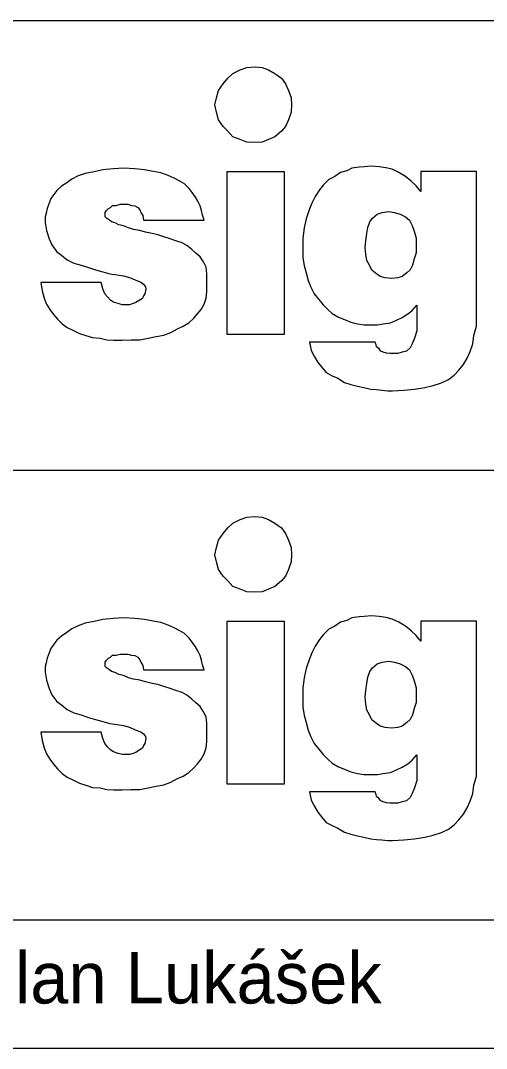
# Model space of a CAD drawing. Extents: x -193 to -151, y 303.3 to 362.7.
# Drawn here: x -158.675 to -156.861, y 343 to 347 of the extents above; entities that cross this region are included whole.
import ezdxf

# ---------------------------------------------------------------- set-up
doc = ezdxf.new("R2010")
doc.units = 0
for name, color, linetype in [('Info o rozpiskách', 7, 'Continuous'), ('popis', 7, 'Continuous'), ('Rozpiska_pole_6', 7, 'Continuous')]:
    doc.layers.add(name, color=color, linetype=linetype)

msp = doc.modelspace()

# ---------------------------------------------------------------- linework, layer by layer
at = {"layer": 'Info o rozpiskách'}
for points in [[(-157.7618, 346.8197), (-157.7338, 346.8178), (-157.7097, 346.8078), (-157.6857, 346.7937), (-157.6597, 346.7757), (-157.6437, 346.7537), (-157.6316, 346.7276), (-157.6216, 346.6996), (-157.6196, 346.6715), (-157.6216, 346.6435), (-157.6316, 346.6134), (-157.6437, 346.5874), (-157.6597, 346.5694), (-157.6857, 346.5473), (-157.7097, 346.5373), (-157.7338, 346.5273), (-157.7618, 346.5253), (-157.7939, 346.5273), (-157.8199, 346.5373), (-157.848, 346.5473), (-157.868, 346.5694), (-157.886, 346.5874), (-157.9041, 346.6134), (-157.9121, 346.6435), (-157.9181, 346.6715), (-157.9121, 346.6996), (-157.9041, 346.7276), (-157.886, 346.7537), (-157.868, 346.7757), (-157.848, 346.7937), (-157.8199, 346.8078), (-157.7939, 346.8178), (-157.7618, 346.8197)], [(-157.7618, 345.0697), (-157.7338, 345.0678), (-157.7097, 345.0578), (-157.6857, 345.0437), (-157.6597, 345.0257), (-157.6437, 345.0037), (-157.6316, 344.9776), (-157.6216, 344.9496), (-157.6196, 344.9215), (-157.6216, 344.8935), (-157.6316, 344.8634), (-157.6437, 344.8374), (-157.6597, 344.8194), (-157.6857, 344.7973), (-157.7097, 344.7873), (-157.7338, 344.7773), (-157.7618, 344.7753), (-157.7939, 344.7773), (-157.8199, 344.7873), (-157.848, 344.7973), (-157.868, 344.8194), (-157.886, 344.8374), (-157.9041, 344.8634), (-157.9121, 344.8935), (-157.9181, 344.9215), (-157.9121, 344.9496), (-157.9041, 344.9776), (-157.886, 345.0037), (-157.868, 345.0257), (-157.848, 345.0437), (-157.8199, 345.0578), (-157.7939, 345.0678), (-157.7618, 345.0697)]]:
    msp.add_lwpolyline(points, dxfattribs=at)
at = {"layer": 'popis'}
for points in [[(-158.1966, 346.2228), (-157.9602, 346.2228), (-157.9662, 346.2428), (-157.9702, 346.2609), (-157.9762, 346.2788), (-157.9842, 346.2969), (-157.9943, 346.3129), (-158.0062, 346.331), (-158.0182, 346.347), (-158.0363, 346.365), (-158.0543, 346.375), (-158.0763, 346.3871), (-158.1004, 346.3971), (-158.1284, 346.4071), (-158.1585, 346.4131), (-158.1925, 346.4191), (-158.2306, 346.4231), (-158.2726, 346.4251), (-158.3147, 346.4231), (-158.3548, 346.4191), (-158.3888, 346.4111), (-158.4229, 346.4051), (-158.451, 346.3951), (-158.475, 346.3831), (-158.495, 346.369), (-158.5151, 346.355), (-158.5331, 346.339), (-158.5451, 346.3229), (-158.5572, 346.3069), (-158.5631, 346.2889), (-158.5712, 346.2688), (-158.5751, 346.2509), (-158.5792, 346.2368), (-158.5792, 346.2147), (-158.5732, 346.1827), (-158.5631, 346.1507), (-158.5531, 346.1266), (-158.5331, 346.1006), (-158.5151, 346.0866), (-158.4931, 346.0685), (-158.467, 346.0565), (-158.439, 346.0485), (-158.4109, 346.0385), (-158.3828, 346.0305), (-158.3548, 346.0225), (-158.3268, 346.0144), (-158.2987, 346.0105), (-158.2747, 346.0065), (-158.2506, 346.0004), (-158.2286, 345.9904), (-158.2066, 345.9824), (-158.1966, 345.9744), (-158.1885, 345.9644), (-158.1865, 345.9544), (-158.1906, 345.9363), (-158.1966, 345.9283), (-158.2006, 345.9183), (-158.2126, 345.9103), (-158.2266, 345.9022), (-158.2366, 345.8983), (-158.2506, 345.8943), (-158.2647, 345.8943), (-158.2787, 345.8943), (-158.2947, 345.8983), (-158.3128, 345.9043), (-158.3228, 345.9103), (-158.3368, 345.9243), (-158.3468, 345.9363), (-158.3548, 345.9563), (-158.3608, 345.9804), (-158.5952, 345.9804), (-158.5912, 345.9484), (-158.5832, 345.9203), (-158.5732, 345.8962), (-158.5612, 345.8762), (-158.5471, 345.8562), (-158.5311, 345.8381), (-158.5131, 345.8202), (-158.4931, 345.8061), (-158.469, 345.7941), (-158.445, 345.7821), (-158.4209, 345.7741), (-158.3949, 345.7661), (-158.3648, 345.764), (-158.3388, 345.758), (-158.3128, 345.756), (-158.2787, 345.756), (-158.2446, 345.758), (-158.2106, 345.758), (-158.1785, 345.764), (-158.1465, 345.77), (-158.1165, 345.7761), (-158.0904, 345.7861), (-158.0643, 345.8001), (-158.0423, 345.8102), (-158.0203, 345.8241), (-158.0002, 345.8422), (-157.9862, 345.8582), (-157.9722, 345.8762), (-157.9602, 345.8962), (-157.9522, 345.9203), (-157.9501, 345.9443), (-157.9501, 345.9684), (-157.9501, 345.9744), (-157.9501, 345.9804), (-157.9501, 345.9864), (-157.9501, 345.9924), (-157.9501, 346.0004), (-157.9501, 346.0065), (-157.9501, 346.0105), (-157.9501, 346.0144), (-157.9522, 346.0405), (-157.9622, 346.0605), (-157.9762, 346.0806), (-157.9922, 346.0946), (-158.0082, 346.1086), (-158.0282, 346.1246), (-158.0463, 346.1347), (-158.0703, 346.1427), (-158.0924, 346.1507), (-158.1165, 346.1587), (-158.1404, 346.1667), (-158.1625, 346.1707), (-158.1885, 346.1767), (-158.2106, 346.1827), (-158.2346, 346.1868), (-158.2547, 346.1928), (-158.2747, 346.2007), (-158.2927, 346.2047), (-158.3067, 346.2128), (-158.3207, 346.2168), (-158.3288, 346.2228), (-158.3407, 346.2308), (-158.3448, 346.2368), (-158.3448, 346.2448), (-158.3448, 346.2528), (-158.3407, 346.2609), (-158.3328, 346.2688), (-158.3247, 346.2729), (-158.3168, 346.2809), (-158.3027, 346.2809), (-158.2867, 346.2849), (-158.2726, 346.2849), (-158.2566, 346.2849), (-158.2426, 346.2809), (-158.2306, 346.2788), (-158.2186, 346.2729), (-158.2106, 346.2628), (-158.2066, 346.2528), (-158.1985, 346.2408), (-158.1966, 346.2228)], [(-157.872, 346.4111), (-157.872, 345.78), (-157.6477, 345.78), (-157.6477, 346.4111), (-157.872, 346.4111)], [(-157.1168, 346.4131), (-157.1168, 346.335), (-157.1349, 346.357), (-157.1549, 346.375), (-157.1769, 346.3931), (-157.203, 346.4091), (-157.229, 346.4211), (-157.253, 346.4271), (-157.2791, 346.4312), (-157.3091, 346.4331), (-157.3372, 346.4312), (-157.3572, 346.4291), (-157.3852, 346.4251), (-157.4053, 346.4151), (-157.4293, 346.4091), (-157.4513, 346.3931), (-157.4754, 346.381), (-157.4954, 346.361), (-157.5115, 346.341), (-157.5275, 346.315), (-157.5415, 346.2889), (-157.5515, 346.2628), (-157.5635, 346.2288), (-157.5715, 346.1928), (-157.5756, 346.1527), (-157.5756, 346.1106), (-157.5756, 346.0765), (-157.5715, 346.0465), (-157.5635, 346.0184), (-157.5555, 345.9884), (-157.5455, 345.9624), (-157.5315, 345.9363), (-157.5134, 345.9143), (-157.4974, 345.8943), (-157.4794, 345.8762), (-157.4613, 345.8602), (-157.4374, 345.8462), (-157.4133, 345.8362), (-157.3893, 345.8262), (-157.3632, 345.8202), (-157.3372, 345.8161), (-157.3091, 345.8161), (-157.285, 345.8161), (-157.263, 345.8202), (-157.235, 345.8241), (-157.2109, 345.8341), (-157.1889, 345.8441), (-157.1669, 345.8582), (-157.1509, 345.8722), (-157.1328, 345.8922), (-157.1328, 345.8341), (-157.1328, 345.7921), (-157.1409, 345.764), (-157.1509, 345.742), (-157.1589, 345.726), (-157.1729, 345.714), (-157.1889, 345.71), (-157.2069, 345.704), (-157.2269, 345.704), (-157.237, 345.704), (-157.251, 345.7059), (-157.263, 345.71), (-157.2731, 345.714), (-157.2791, 345.7219), (-157.2891, 345.73), (-157.2911, 345.738), (-157.2951, 345.748), (-157.5495, 345.748), (-157.5435, 345.7159), (-157.5315, 345.694), (-157.5175, 345.6699), (-157.5034, 345.6519), (-157.4854, 345.6299), (-157.4613, 345.6178), (-157.4393, 345.6078), (-157.4133, 345.5918), (-157.3893, 345.5837), (-157.3632, 345.5778), (-157.3391, 345.5718), (-157.3111, 345.5658), (-157.2891, 345.5637), (-157.269, 345.5617), (-157.245, 345.5597), (-157.2269, 345.5597), (-157.1829, 345.5617), (-157.1409, 345.5658), (-157.1008, 345.5718), (-157.0687, 345.5797), (-157.0367, 345.5897), (-157.0086, 345.6038), (-156.9866, 345.6198), (-156.9686, 345.6399), (-156.9505, 345.6619), (-156.9365, 345.6859), (-156.9245, 345.7119), (-156.9145, 345.742), (-156.9105, 345.7741), (-156.9005, 345.8102), (-156.9005, 345.8482), (-156.9005, 345.8922), (-156.9005, 346.4131), (-157.1168, 346.4131)], [(-157.241, 346.2568), (-157.219, 346.2528), (-157.1969, 346.2468), (-157.1769, 346.2368), (-157.1609, 346.2228), (-157.1509, 346.2028), (-157.1428, 346.1807), (-157.1349, 346.1527), (-157.1349, 346.1226), (-157.1349, 346.0966), (-157.1428, 346.0725), (-157.1488, 346.0485), (-157.1589, 346.0305), (-157.1709, 346.0184), (-157.1889, 346.0044), (-157.2069, 345.9984), (-157.231, 345.9965), (-157.255, 345.9984), (-157.275, 346.0044), (-157.2951, 346.0184), (-157.3071, 346.0285), (-157.3171, 346.0485), (-157.3271, 346.0665), (-157.3312, 346.0906), (-157.3331, 346.1166), (-157.3312, 346.1447), (-157.3271, 346.1707), (-157.3231, 346.1947), (-157.3152, 346.2168), (-157.3051, 346.2308), (-157.2871, 346.2468), (-157.2671, 346.2528), (-157.241, 346.2568)], [(-157.1168, 344.6631), (-157.1168, 344.585), (-157.1349, 344.607), (-157.1549, 344.625), (-157.1769, 344.6431), (-157.203, 344.6591), (-157.229, 344.6711), (-157.253, 344.6771), (-157.2791, 344.6812), (-157.3091, 344.6831), (-157.3372, 344.6812), (-157.3572, 344.6791), (-157.3852, 344.6751), (-157.4053, 344.6651), (-157.4293, 344.6591), (-157.4513, 344.6431), (-157.4754, 344.631), (-157.4954, 344.611), (-157.5115, 344.591), (-157.5275, 344.565), (-157.5415, 344.5389), (-157.5515, 344.5128), (-157.5635, 344.4788), (-157.5715, 344.4428), (-157.5756, 344.4027), (-157.5756, 344.3606), (-157.5756, 344.3265), (-157.5715, 344.2965), (-157.5635, 344.2684), (-157.5555, 344.2384), (-157.5455, 344.2124), (-157.5315, 344.1863), (-157.5134, 344.1643), (-157.4974, 344.1443), (-157.4794, 344.1262), (-157.4613, 344.1102), (-157.4374, 344.0962), (-157.4133, 344.0862), (-157.3893, 344.0762), (-157.3632, 344.0702), (-157.3372, 344.0661), (-157.3091, 344.0661), (-157.285, 344.0661), (-157.263, 344.0702), (-157.235, 344.0741), (-157.2109, 344.0841), (-157.1889, 344.0941), (-157.1669, 344.1082), (-157.1509, 344.1222), (-157.1328, 344.1422), (-157.1328, 344.0841), (-157.1328, 344.0421), (-157.1409, 344.014), (-157.1509, 343.992), (-157.1589, 343.976), (-157.1729, 343.964), (-157.1889, 343.96), (-157.2069, 343.954), (-157.2269, 343.954), (-157.237, 343.954), (-157.251, 343.9559), (-157.263, 343.96), (-157.2731, 343.964), (-157.2791, 343.9719), (-157.2891, 343.98), (-157.2911, 343.988), (-157.2951, 343.998), (-157.5495, 343.998), (-157.5435, 343.9659), (-157.5315, 343.944), (-157.5175, 343.9199), (-157.5034, 343.9019), (-157.4854, 343.8799), (-157.4613, 343.8678), (-157.4393, 343.8578), (-157.4133, 343.8418), (-157.3893, 343.8337), (-157.3632, 343.8278), (-157.3391, 343.8218), (-157.3111, 343.8158), (-157.2891, 343.8137), (-157.269, 343.8117), (-157.245, 343.8097), (-157.2269, 343.8097), (-157.1829, 343.8117), (-157.1409, 343.8158), (-157.1008, 343.8218), (-157.0687, 343.8297), (-157.0367, 343.8397), (-157.0086, 343.8538), (-156.9866, 343.8698), (-156.9686, 343.8899), (-156.9505, 343.9119), (-156.9365, 343.9359), (-156.9245, 343.9619), (-156.9145, 343.992), (-156.9105, 344.0241), (-156.9005, 344.0602), (-156.9005, 344.0982), (-156.9005, 344.1422), (-156.9005, 344.6631), (-157.1168, 344.6631)], [(-158.1966, 344.4728), (-157.9602, 344.4728), (-157.9662, 344.4928), (-157.9702, 344.5109), (-157.9762, 344.5288), (-157.9842, 344.5469), (-157.9943, 344.5629), (-158.0062, 344.581), (-158.0182, 344.597), (-158.0363, 344.615), (-158.0543, 344.625), (-158.0763, 344.6371), (-158.1004, 344.6471), (-158.1284, 344.6571), (-158.1585, 344.6631), (-158.1925, 344.6691), (-158.2306, 344.6731), (-158.2726, 344.6751), (-158.3147, 344.6731), (-158.3548, 344.6691), (-158.3888, 344.6611), (-158.4229, 344.6551), (-158.451, 344.6451), (-158.475, 344.6331), (-158.495, 344.619), (-158.5151, 344.605), (-158.5331, 344.589), (-158.5451, 344.5729), (-158.5572, 344.5569), (-158.5631, 344.5389), (-158.5712, 344.5188), (-158.5751, 344.5009), (-158.5792, 344.4868), (-158.5792, 344.4647), (-158.5732, 344.4327), (-158.5631, 344.4007), (-158.5531, 344.3766), (-158.5331, 344.3506), (-158.5151, 344.3366), (-158.4931, 344.3185), (-158.467, 344.3065), (-158.439, 344.2985), (-158.4109, 344.2885), (-158.3828, 344.2805), (-158.3548, 344.2725), (-158.3268, 344.2644), (-158.2987, 344.2605), (-158.2747, 344.2565), (-158.2506, 344.2504), (-158.2286, 344.2404), (-158.2066, 344.2324), (-158.1966, 344.2244), (-158.1885, 344.2144), (-158.1865, 344.2044), (-158.1906, 344.1863), (-158.1966, 344.1783), (-158.2006, 344.1683), (-158.2126, 344.1603), (-158.2266, 344.1522), (-158.2366, 344.1483), (-158.2506, 344.1443), (-158.2647, 344.1443), (-158.2787, 344.1443), (-158.2947, 344.1483), (-158.3128, 344.1543), (-158.3228, 344.1603), (-158.3368, 344.1743), (-158.3468, 344.1863), (-158.3548, 344.2063), (-158.3608, 344.2304), (-158.5952, 344.2304), (-158.5912, 344.1984), (-158.5832, 344.1703), (-158.5732, 344.1462), (-158.5612, 344.1262), (-158.5471, 344.1062), (-158.5311, 344.0881), (-158.5131, 344.0702), (-158.4931, 344.0561), (-158.469, 344.0441), (-158.445, 344.0321), (-158.4209, 344.0241), (-158.3949, 344.0161), (-158.3648, 344.014), (-158.3388, 344.008), (-158.3128, 344.006), (-158.2787, 344.006), (-158.2446, 344.008), (-158.2106, 344.008), (-158.1785, 344.014), (-158.1465, 344.02), (-158.1165, 344.0261), (-158.0904, 344.0361), (-158.0643, 344.0501), (-158.0423, 344.0602), (-158.0203, 344.0741), (-158.0002, 344.0922), (-157.9862, 344.1082), (-157.9722, 344.1262), (-157.9602, 344.1462), (-157.9522, 344.1703), (-157.9501, 344.1943), (-157.9501, 344.2184), (-157.9501, 344.2244), (-157.9501, 344.2304), (-157.9501, 344.2364), (-157.9501, 344.2424), (-157.9501, 344.2504), (-157.9501, 344.2565), (-157.9501, 344.2605), (-157.9501, 344.2644), (-157.9522, 344.2905), (-157.9622, 344.3105), (-157.9762, 344.3306), (-157.9922, 344.3446), (-158.0082, 344.3586), (-158.0282, 344.3746), (-158.0463, 344.3847), (-158.0703, 344.3927), (-158.0924, 344.4007), (-158.1165, 344.4087), (-158.1404, 344.4167), (-158.1625, 344.4207), (-158.1885, 344.4267), (-158.2106, 344.4327), (-158.2346, 344.4368), (-158.2547, 344.4428), (-158.2747, 344.4507), (-158.2927, 344.4547), (-158.3067, 344.4628), (-158.3207, 344.4668), (-158.3288, 344.4728), (-158.3407, 344.4808), (-158.3448, 344.4868), (-158.3448, 344.4948), (-158.3448, 344.5028), (-158.3407, 344.5109), (-158.3328, 344.5188), (-158.3247, 344.5229), (-158.3168, 344.5309), (-158.3027, 344.5309), (-158.2867, 344.5349), (-158.2726, 344.5349), (-158.2566, 344.5349), (-158.2426, 344.5309), (-158.2306, 344.5288), (-158.2186, 344.5229), (-158.2106, 344.5128), (-158.2066, 344.5028), (-158.1985, 344.4908), (-158.1966, 344.4728)], [(-157.872, 344.6611), (-157.872, 344.03), (-157.6477, 344.03), (-157.6477, 344.6611), (-157.872, 344.6611)], [(-157.241, 344.5068), (-157.219, 344.5028), (-157.1969, 344.4968), (-157.1769, 344.4868), (-157.1609, 344.4728), (-157.1509, 344.4528), (-157.1428, 344.4307), (-157.1349, 344.4027), (-157.1349, 344.3726), (-157.1349, 344.3466), (-157.1428, 344.3225), (-157.1488, 344.2985), (-157.1589, 344.2805), (-157.1709, 344.2684), (-157.1889, 344.2544), (-157.2069, 344.2484), (-157.231, 344.2465), (-157.255, 344.2484), (-157.275, 344.2544), (-157.2951, 344.2684), (-157.3071, 344.2785), (-157.3171, 344.2985), (-157.3271, 344.3165), (-157.3312, 344.3406), (-157.3331, 344.3666), (-157.3312, 344.3947), (-157.3271, 344.4207), (-157.3231, 344.4447), (-157.3152, 344.4668), (-157.3051, 344.4808), (-157.2871, 344.4968), (-157.2671, 344.5028), (-157.241, 344.5068)]]:
    msp.add_lwpolyline(points, dxfattribs=at)
at = {"layer": 'Rozpiska_pole_6'}
for p, q in [((-170, 345.25), (-153, 345.25)), ((-170, 343.5), (-153, 343.5))]:
    msp.add_line(p, q, dxfattribs=at)
msp.add_lwpolyline([(-170, 347), (-153, 347), (-153, 343), (-170, 343)], close=True, dxfattribs=at)

# ---------------------------------------------------------------- texts
msp.add_text('Ing. Milan Lukášek', height=0.2, dxfattribs=at).set_placement((-159.4991, 343.175))

doc.saveas('drawing.dxf')
